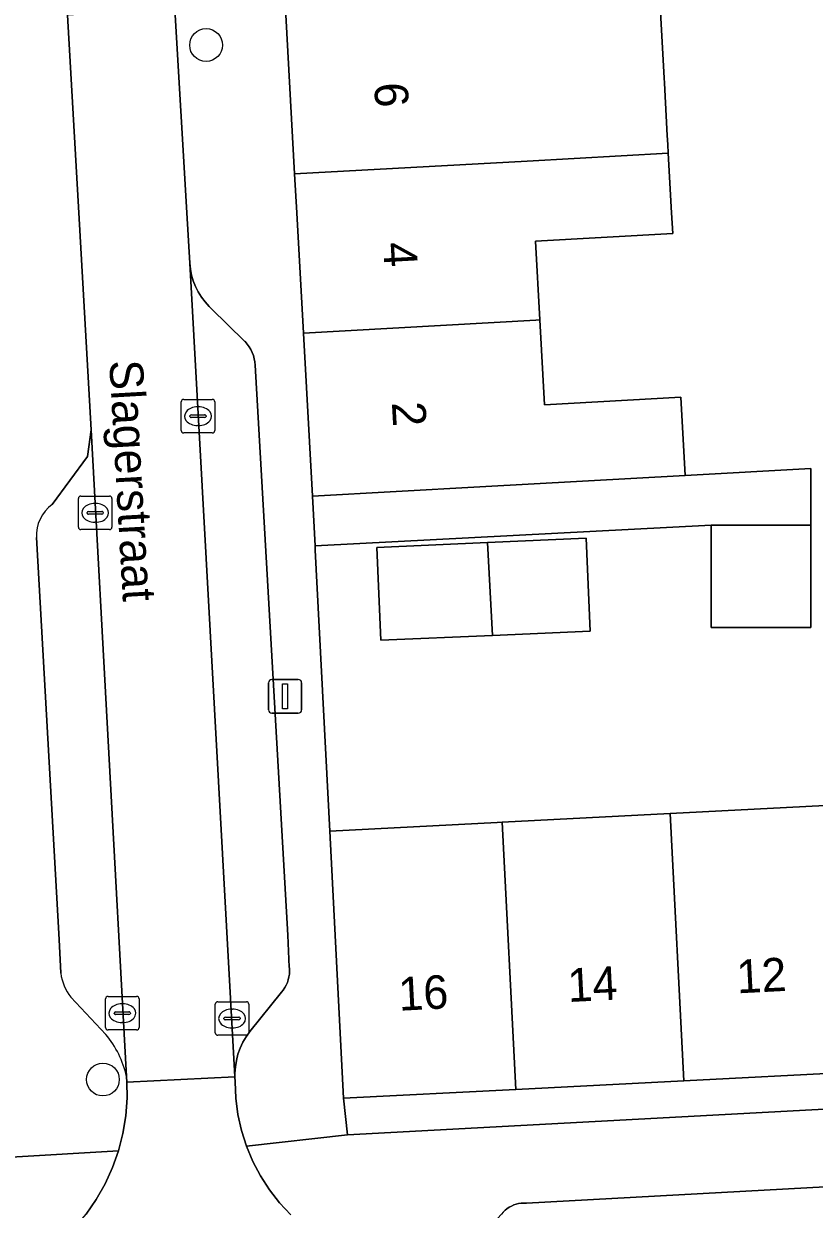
# Model space of a CAD drawing. Extents: x 160856 to 161310, y 384024 to 384878.
# Drawn here: x 161059.68 to 161083.27, y 384720.28 to 384755.64 of the extents above; entities that cross this region are included whole.
import ezdxf

# ---------------------------------------------------------------- set-up
doc = ezdxf.new("R2010")
doc.units = 0
for name, color, linetype in [('IMGEO_Boom', 7, 'Continuous'), ('IMGEO_Erf', 7, 'Continuous'), ('IMGEO_Kolk', 7, 'Continuous'), ('IMGEO_Lichtmast', 7, 'Continuous'), ('IMGEO_Muur', 7, 'Continuous'), ('IMGEO_Openbare_ruimte_label', 7, 'Continuous'), ('IMGEO_Pand', 7, 'Continuous'), ('IMGEO_Pand_nummerreeks', 7, 'Continuous'), ('IMGEO_Parkeervlak_open', 7, 'Continuous'), ('IMGEO_Rijbaan_lokaal_open', 7, 'Continuous'), ('IMGEO_Voetpad_open', 7, 'Continuous')]:
    doc.layers.add(name, color=color, linetype=linetype)

msp = doc.modelspace()

# ---------------------------------------------------------------- linework, layer by layer
at = {"layer": 'IMGEO_Boom'}
for centre in [(161065.12, 384755.001), (161062.042, 384724.148)]:
    msp.add_circle(centre, 0.489, dxfattribs=at)
at = {"layer": 'IMGEO_Erf'}
msp.add_lwpolyline([(161078.652, 384756.524), (161078.791, 384754.027), (161078.8, 384753.863), (161078.881, 384752.303), (161078.896, 384752.04), (161078.91, 384751.777), (161079.01, 384750), (161079.044, 384749.384), (161074.947, 384749.156), (161075.078, 384746.803), (161075.218, 384744.275), (161079.282, 384744.501), (161079.412, 384742.164), (161083.167, 384742.372), (161083.167, 384740.682), (161083.167, 384737.63), (161080.192, 384737.63), (161080.192, 384740.682), (161068.371, 384740.071), (161068.378, 384739.94), (161068.814, 384731.561), (161073.808, 384731.818), (161073.951, 384731.825), (161078.967, 384732.084), (161083.983, 384732.342)], dxfattribs=at)
for points in [[(161076.457, 384740.291), (161076.577, 384737.522), (161073.664, 384737.396), (161070.332, 384737.251), (161070.212, 384740.02), (161073.521, 384740.164)], [(161109.597, 384725.668), (161104.46, 384725.404), (161099.443, 384725.146), (161094.427, 384724.888), (161089.411, 384724.63), (161084.394, 384724.371), (161079.378, 384724.113), (161074.362, 384723.855), (161069.224, 384723.591), (161069.34, 384722.503), (161109.616, 384724.666)]]:
    msp.add_lwpolyline(points, close=True, dxfattribs=at)
at = {"layer": 'IMGEO_Kolk'}
for p, q in [((161064.453, 384744.433), (161065.305, 384744.433)), ((161064.378, 384743.507), (161064.378, 384744.359)), ((161064.866, 384744.213), (161064.891, 384744.213)), ((161065.379, 384744.359), (161065.379, 384743.507)), ((161064.637, 384743.927), (161064.637, 384743.939)), ((161065.075, 384743.89), (161064.677, 384743.89)), ((161064.68, 384743.976), (161065.078, 384743.976)), ((161065.121, 384743.939), (161065.121, 384743.927)), ((161065.305, 384743.433), (161064.453, 384743.433)), ((161064.889, 384743.653), (161064.864, 384743.653)), ((161061.385, 384741.55), (161062.237, 384741.55)), ((161061.31, 384740.624), (161061.31, 384741.476)), ((161061.798, 384741.33), (161061.823, 384741.33)), ((161062.311, 384741.476), (161062.311, 384740.624)), ((161061.569, 384741.044), (161061.569, 384741.056)), ((161062.007, 384741.007), (161061.609, 384741.007)), ((161061.612, 384741.093), (161062.01, 384741.093)), ((161062.053, 384741.056), (161062.053, 384741.044)), ((161062.237, 384740.55), (161061.385, 384740.55)), ((161061.821, 384740.77), (161061.796, 384740.77)), ((161062.12, 384725.702), (161062.12, 384726.554)), ((161062.195, 384726.628), (161063.047, 384726.628)), ((161062.608, 384726.408), (161062.633, 384726.408)), ((161063.121, 384726.554), (161063.121, 384725.702)), ((161065.394, 384725.543), (161065.394, 384726.395)), ((161065.469, 384726.469), (161066.321, 384726.469)), ((161066.395, 384726.395), (161066.395, 384725.543)), ((161062.379, 384726.122), (161062.379, 384726.134)), ((161062.817, 384726.085), (161062.419, 384726.085)), ((161062.422, 384726.171), (161062.82, 384726.171)), ((161062.863, 384726.134), (161062.863, 384726.122)), ((161065.696, 384726.012), (161066.094, 384726.012)), ((161065.882, 384726.249), (161065.907, 384726.249)), ((161062.631, 384725.848), (161062.606, 384725.848)), ((161065.653, 384725.963), (161065.653, 384725.975)), ((161066.091, 384725.926), (161065.693, 384725.926)), ((161065.905, 384725.689), (161065.88, 384725.689)), ((161066.137, 384725.975), (161066.137, 384725.963)), ((161063.047, 384725.628), (161062.195, 384725.628)), ((161066.321, 384725.469), (161065.469, 384725.469))]:
    msp.add_line(p, q, dxfattribs=at)
for points in [[(161064.453, 384744.433), (161065.305, 384744.433)], [(161064.378, 384743.507), (161064.378, 384744.359)], [(161065.379, 384744.359), (161065.379, 384743.507)], [(161065.305, 384743.433), (161064.453, 384743.433)], [(161061.385, 384741.55), (161062.237, 384741.55)], [(161061.31, 384740.624), (161061.31, 384741.476)], [(161062.311, 384741.476), (161062.311, 384740.624)], [(161062.237, 384740.55), (161061.385, 384740.55)], [(161062.12, 384725.702), (161062.12, 384726.554)], [(161062.195, 384726.628), (161063.047, 384726.628)], [(161063.121, 384726.554), (161063.121, 384725.702)], [(161065.394, 384725.543), (161065.394, 384726.395)], [(161065.469, 384726.469), (161066.321, 384726.469)], [(161066.395, 384726.395), (161066.395, 384725.543)], [(161063.047, 384725.628), (161062.195, 384725.628)], [(161066.321, 384725.469), (161065.469, 384725.469)]]:
    msp.add_lwpolyline(points, dxfattribs=at)
for centre, radius, start, end in [((161064.455, 384744.357), 0.0765, 91.552, 178.448), ((161064.455, 384744.357), 0.0765, 91.552, 178.448), ((161065.303, 384744.357), 0.0765, 1.552, 88.448), ((161065.303, 384744.357), 0.0765, 1.552, 88.448), ((161064.677, 384743.936), 0.0403, 85.8775, 175.7526), ((161064.674, 384743.926), 0.0366, 178.938, 274.7102), ((161065.078, 384743.933), 0.043, 264.8664, 352.4533), ((161065.082, 384743.938), 0.0386, 1.7309, 96.639), ((161064.455, 384743.509), 0.0765, 181.552, 268.448), ((161064.455, 384743.509), 0.0765, 181.552, 268.448), ((161065.303, 384743.509), 0.0765, 271.552, 358.448), ((161065.303, 384743.509), 0.0765, 271.552, 358.448), ((161061.387, 384741.474), 0.0765, 91.552, 178.448), ((161061.387, 384741.474), 0.0765, 91.552, 178.448), ((161062.235, 384741.474), 0.0765, 1.552, 88.448), ((161062.235, 384741.474), 0.0765, 1.552, 88.448), ((161061.609, 384741.053), 0.0403, 85.8775, 175.7526), ((161061.606, 384741.043), 0.0366, 178.938, 274.7102), ((161062.01, 384741.05), 0.043, 264.8664, 352.4533), ((161062.014, 384741.055), 0.0386, 1.7309, 96.639), ((161061.387, 384740.626), 0.0765, 181.552, 268.448), ((161061.387, 384740.626), 0.0765, 181.552, 268.448), ((161062.235, 384740.626), 0.0765, 271.552, 358.448), ((161062.235, 384740.626), 0.0765, 271.552, 358.448), ((161062.197, 384726.552), 0.0765, 91.552, 178.448), ((161062.197, 384726.552), 0.0765, 91.552, 178.448), ((161063.045, 384726.552), 0.0765, 1.552, 88.448), ((161063.045, 384726.552), 0.0765, 1.552, 88.448), ((161065.471, 384726.393), 0.0765, 91.552, 178.448), ((161065.471, 384726.393), 0.0765, 91.552, 178.448), ((161066.319, 384726.393), 0.0765, 1.552, 88.448), ((161066.319, 384726.393), 0.0765, 1.552, 88.448), ((161062.419, 384726.131), 0.0403, 85.8775, 175.7526), ((161062.416, 384726.121), 0.0366, 178.938, 274.7102), ((161062.82, 384726.128), 0.043, 264.8664, 352.4533), ((161062.824, 384726.133), 0.0386, 1.7309, 96.639), ((161065.693, 384725.972), 0.0403, 85.8775, 175.7526), ((161066.098, 384725.974), 0.0386, 1.7309, 96.639), ((161062.197, 384725.704), 0.0765, 181.552, 268.448), ((161062.197, 384725.704), 0.0765, 181.552, 268.448), ((161063.045, 384725.704), 0.0765, 271.552, 358.448), ((161063.045, 384725.704), 0.0765, 271.552, 358.448), ((161065.69, 384725.962), 0.0366, 178.938, 274.7102), ((161066.094, 384725.969), 0.043, 264.8664, 352.4533), ((161065.471, 384725.545), 0.0765, 181.552, 268.448), ((161065.471, 384725.545), 0.0765, 181.552, 268.448), ((161066.319, 384725.545), 0.0765, 271.552, 358.448), ((161066.319, 384725.545), 0.0765, 271.552, 358.448)]:
    msp.add_arc(centre, radius, start, end, dxfattribs=at)
for centre, major_axis, ratio, start_param, end_param in [((161064.865, 384743.933), (-0.387, 0.002), 0.722429, 4.712389, 7.853982), ((161064.89, 384743.933), (-0.39, 0.002), 0.717154, 1.570796, 4.712389), ((161061.797, 384741.05), (-0.387, 0.002), 0.722429, 4.712389, 7.853982), ((161061.822, 384741.05), (-0.39, 0.002), 0.717154, 1.570796, 4.712389), ((161062.607, 384726.128), (-0.387, 0.002), 0.722429, 4.712389, 7.853982), ((161062.632, 384726.128), (-0.39, 0.002), 0.717154, 1.570796, 4.712389), ((161065.881, 384725.969), (-0.387, 0.002), 0.722429, 4.712389, 7.853982), ((161065.906, 384725.969), (-0.39, 0.002), 0.717154, 1.570796, 4.712389)]:
    msp.add_ellipse(centre, major_axis=major_axis, ratio=ratio, start_param=start_param, end_param=end_param, dxfattribs=at)
at = {"layer": 'IMGEO_Lichtmast'}
for p, q in [((161066.982, 384735.178), (161066.982, 384735.978)), ((161066.982, 384735.978), (161066.982, 384735.178)), ((161067.082, 384736.078), (161067.872, 384736.078)), ((161067.872, 384736.078), (161067.082, 384736.078)), ((161067.972, 384735.978), (161067.972, 384735.178)), ((161067.972, 384735.178), (161067.972, 384735.978)), ((161067.872, 384735.078), (161067.082, 384735.078)), ((161067.082, 384735.078), (161067.872, 384735.078))]:
    msp.add_line(p, q, dxfattribs=at)
msp.add_lwpolyline([(161067.402, 384735.953), (161067.552, 384735.953), (161067.552, 384735.203), (161067.402, 384735.203), (161067.402, 384735.953)], dxfattribs=at)
for centre, start, end in [((161067.082, 384735.978), 90, 180), ((161067.082, 384735.978), 90, 180), ((161067.872, 384735.978), 0, 90), ((161067.872, 384735.978), 360, 90), ((161067.082, 384735.178), 180, 270), ((161067.082, 384735.178), 180, 270), ((161067.872, 384735.178), 270, 0), ((161067.872, 384735.178), 270, 0)]:
    msp.add_arc(centre, 0.1, start, end, dxfattribs=at)
at = {"layer": 'IMGEO_Muur'}
msp.add_lwpolyline([(161068.378, 384739.94), (161068.814, 384731.561)], dxfattribs=at)
at = {"layer": 'IMGEO_Pand'}
for points in [[(161078.652, 384756.524), (161074.639, 384756.3), (161074.434, 384756.289), (161067.497, 384755.903), (161067.761, 384751.157), (161074.698, 384751.543), (161078.91, 384751.777), (161078.896, 384752.04), (161078.881, 384752.303), (161078.8, 384753.863), (161078.791, 384754.027)], [(161075.078, 384746.803), (161074.947, 384749.156), (161079.044, 384749.384), (161079.01, 384750), (161078.91, 384751.777), (161074.698, 384751.543), (161067.761, 384751.157), (161067.825, 384750), (161068.025, 384746.411), (161074.962, 384746.797)], [(161075.078, 384746.803), (161074.962, 384746.797), (161068.025, 384746.411), (161068.295, 384741.546), (161073.288, 384741.824), (161079.412, 384742.164), (161079.282, 384744.501), (161075.218, 384744.275)], [(161083.167, 384740.682), (161080.192, 384740.682), (161080.192, 384737.63), (161083.167, 384737.63)], [(161073.521, 384740.164), (161070.212, 384740.02), (161070.332, 384737.251), (161073.664, 384737.396)], [(161073.521, 384740.164), (161073.664, 384737.396), (161076.577, 384737.522), (161076.457, 384740.291)], [(161074.362, 384723.855), (161079.378, 384724.113), (161078.967, 384732.084), (161073.951, 384731.825)], [(161083.983, 384732.342), (161078.967, 384732.084), (161079.378, 384724.113), (161084.394, 384724.371)], [(161074.362, 384723.855), (161073.951, 384731.825), (161073.808, 384731.818), (161068.814, 384731.561), (161069.224, 384723.591)]]:
    msp.add_lwpolyline(points, close=True, dxfattribs=at)
at = {"layer": 'IMGEO_Parkeervlak_open'}
msp.add_lwpolyline([(161064.63, 384748.494), (161065.98, 384724.229), (161065.98, 384724.336), (161065.994, 384724.527), (161066.024, 384724.717), (161066.072, 384724.904), (161066.136, 384725.085), (161066.216, 384725.26), (161066.311, 384725.427), (161066.421, 384725.585), (161067.368, 384726.751), (161067.422, 384726.818), (161067.47, 384726.89), (161067.511, 384726.966), (161067.545, 384727.045), (161067.572, 384727.126), (161067.592, 384727.21), (161067.604, 384727.296), (161067.608, 384727.382), (161067.605, 384727.468), (161067.602, 384727.497), (161067.557, 384728.452), (161066.584, 384745.451), (161066.575, 384745.549), (161066.558, 384745.645), (161066.532, 384745.74), (161066.497, 384745.832), (161066.455, 384745.921), (161066.405, 384746.005), (161066.347, 384746.085), (161066.283, 384746.159), (161066.271, 384746.171), (161065.276, 384747.148), (161065.215, 384747.207), (161065.093, 384747.34), (161064.984, 384747.484), (161064.888, 384747.637), (161064.806, 384747.798), (161064.739, 384747.965), (161064.687, 384748.138), (161064.65, 384748.315)], close=True, dxfattribs=at)
for points in [[(161062.749, 384724.24), (161061.691, 384743.529), (161061.583, 384742.73), (161060.529, 384741.299)], [(161060.055, 384740.313), (161060.736, 384728.324), (161060.782, 384727.319)], [(161061.086, 384726.606), (161062.129, 384725.496)], [(161116.687, 384722.757), (161074.676, 384720.464), (161074.599, 384720.466), (161074.523, 384720.462), (161074.447, 384720.451), (161074.373, 384720.433), (161074.3, 384720.408), (161074.23, 384720.377), (161074.163, 384720.34), (161074.099, 384720.297), (161074.04, 384720.249), (161073.985, 384720.195), (161073.935, 384720.136), (161072.919, 384719.041), (161072.756, 384718.927), (161072.538, 384718.799), (161072.311, 384718.692), (161072.074, 384718.605), (161071.831, 384718.54), (161119.802, 384721.162)]]:
    msp.add_lwpolyline(points, dxfattribs=at)
for centre, radius, start, end in [((161061.186, 384740.376), 1.132, 125.4381, 183.2119), ((161062.268, 384727.531), 1.501, 188.1325, 218.0512), ((161059.774, 384723.552), 3.054, 13.014, 39.5307)]:
    msp.add_arc(centre, radius, start, end, dxfattribs=at)
at = {"layer": 'IMGEO_Rijbaan_lokaal_open'}
msp.add_lwpolyline([(161065.98, 384724.229), (161064.63, 384748.494), (161064.543, 384750), (161064.192, 384756.072), (161060.988, 384755.894), (161061.323, 384750), (161061.691, 384743.529), (161062.749, 384724.24), (161062.758, 384724.074)], close=True, dxfattribs=at)
msp.add_lwpolyline([(161067.648, 384720.117), (161067.312, 384720.475), (161067.009, 384720.861), (161066.742, 384721.273), (161066.513, 384721.708), (161066.324, 384722.161), (161066.175, 384722.629), (161066.069, 384723.108), (161066.007, 384723.595), (161065.988, 384724.086), (161065.98, 384724.229), (161062.758, 384724.074), (161062.764, 384723.604), (161062.726, 384723.071), (161062.64, 384722.544), (161062.508, 384722.027), (161062.329, 384721.523), (161062.107, 384721.037), (161061.842, 384720.573), (161061.537, 384720.135)], dxfattribs=at)
at = {"layer": 'IMGEO_Voetpad_open'}
for points in [[(161057.215, 384760.131), (161057.487, 384755.383), (161057.759, 384750.635), (161057.795, 384750), (161058.03, 384745.887), (161058.309, 384741.02), (161058.391, 384739.448), (161058.841, 384730.88), (161059.287, 384722.877), (161059.302, 384721.83), (161062.508, 384722.027), (161062.64, 384722.544), (161062.726, 384723.071), (161062.764, 384723.604), (161062.758, 384724.074), (161062.749, 384724.24)], [(161060.529, 384741.299), (161061.583, 384742.73), (161061.691, 384743.529), (161061.323, 384750), (161060.988, 384755.894), (161060.837, 384758.55), (161060.831, 384758.662)], [(161064.192, 384756.072), (161064.543, 384750), (161064.63, 384748.494), (161064.65, 384748.315), (161064.687, 384748.138), (161064.739, 384747.965), (161064.806, 384747.798), (161064.888, 384747.637), (161064.984, 384747.484), (161065.093, 384747.34), (161065.215, 384747.207), (161065.276, 384747.148), (161066.271, 384746.171), (161066.283, 384746.159), (161066.347, 384746.085), (161066.405, 384746.005), (161066.455, 384745.921), (161066.497, 384745.832), (161066.532, 384745.74), (161066.558, 384745.645), (161066.575, 384745.549), (161066.584, 384745.451), (161067.557, 384728.452), (161067.602, 384727.497), (161067.605, 384727.468), (161067.608, 384727.382), (161067.604, 384727.296), (161067.592, 384727.21), (161067.572, 384727.126), (161067.545, 384727.045), (161067.511, 384726.966), (161067.47, 384726.89), (161067.422, 384726.818), (161067.368, 384726.751), (161066.421, 384725.585), (161066.311, 384725.427), (161066.216, 384725.26), (161066.136, 384725.085), (161066.072, 384724.904), (161066.024, 384724.717), (161065.994, 384724.527), (161065.98, 384724.336), (161065.98, 384724.229), (161065.988, 384724.086), (161066.007, 384723.595), (161066.069, 384723.108), (161066.175, 384722.629), (161066.324, 384722.161), (161069.34, 384722.503), (161069.224, 384723.591), (161068.814, 384731.561), (161068.378, 384739.94), (161068.371, 384740.071), (161068.295, 384741.546), (161068.025, 384746.411), (161067.825, 384750), (161067.761, 384751.157), (161067.497, 384755.903)], [(161060.782, 384727.319), (161060.736, 384728.324), (161060.055, 384740.313)], [(161062.129, 384725.496), (161061.086, 384726.606)], [(161109.616, 384724.666), (161069.34, 384722.503), (161066.324, 384722.161), (161066.513, 384721.708), (161066.742, 384721.273), (161067.009, 384720.861), (161067.312, 384720.475), (161067.648, 384720.117)], [(161074.04, 384720.249), (161074.099, 384720.297), (161074.163, 384720.34), (161074.23, 384720.377), (161074.3, 384720.408), (161074.373, 384720.433), (161074.447, 384720.451), (161074.523, 384720.462), (161074.599, 384720.466), (161074.676, 384720.464), (161116.687, 384722.757)], [(161061.194, 384719.726), (161061.537, 384720.135), (161061.842, 384720.573), (161062.107, 384721.037), (161062.329, 384721.523), (161062.508, 384722.027), (161059.302, 384721.83), (161018.927, 384719.697), (161018.857, 384720.62), (161017.413, 384721.551), (161013.814, 384716.265)]]:
    msp.add_lwpolyline(points, dxfattribs=at)
msp.add_lwpolyline([(161079.412, 384742.164), (161073.288, 384741.824), (161068.295, 384741.546), (161068.371, 384740.071), (161080.192, 384740.682), (161083.167, 384740.682), (161083.167, 384742.372)], close=True, dxfattribs=at)
for centre, radius, start, end in [((161061.186, 384740.376), 1.132, 125.4381, 183.2119), ((161062.268, 384727.531), 1.501, 188.1325, 218.0512), ((161059.774, 384723.552), 3.054, 13.014, 39.5307)]:
    msp.add_arc(centre, radius, start, end, dxfattribs=at)

# ---------------------------------------------------------------- texts
at = {"layer": 'IMGEO_Openbare_ruimte_label'}
msp.add_text('Slagerstraat', height=1, rotation=273.2689, dxfattribs=at).set_placement((161062.229, 384745.586))
at = {"layer": 'IMGEO_Pand_nummerreeks'}
for s, rotation, p in [('6', 273.1797, (161070.134, 384753.86)), ('4', 273.1815, (161070.399, 384749.1)), ('2', 273.1815, (161070.663, 384744.342)), ('12', 2.945, (161080.974, 384726.719)), ('14', 2.945, (161075.93, 384726.46)), ('16', 2.945, (161070.883, 384726.2))]:
    msp.add_text(s, height=1, rotation=rotation, dxfattribs=at).set_placement(p)

doc.saveas('drawing.dxf')
